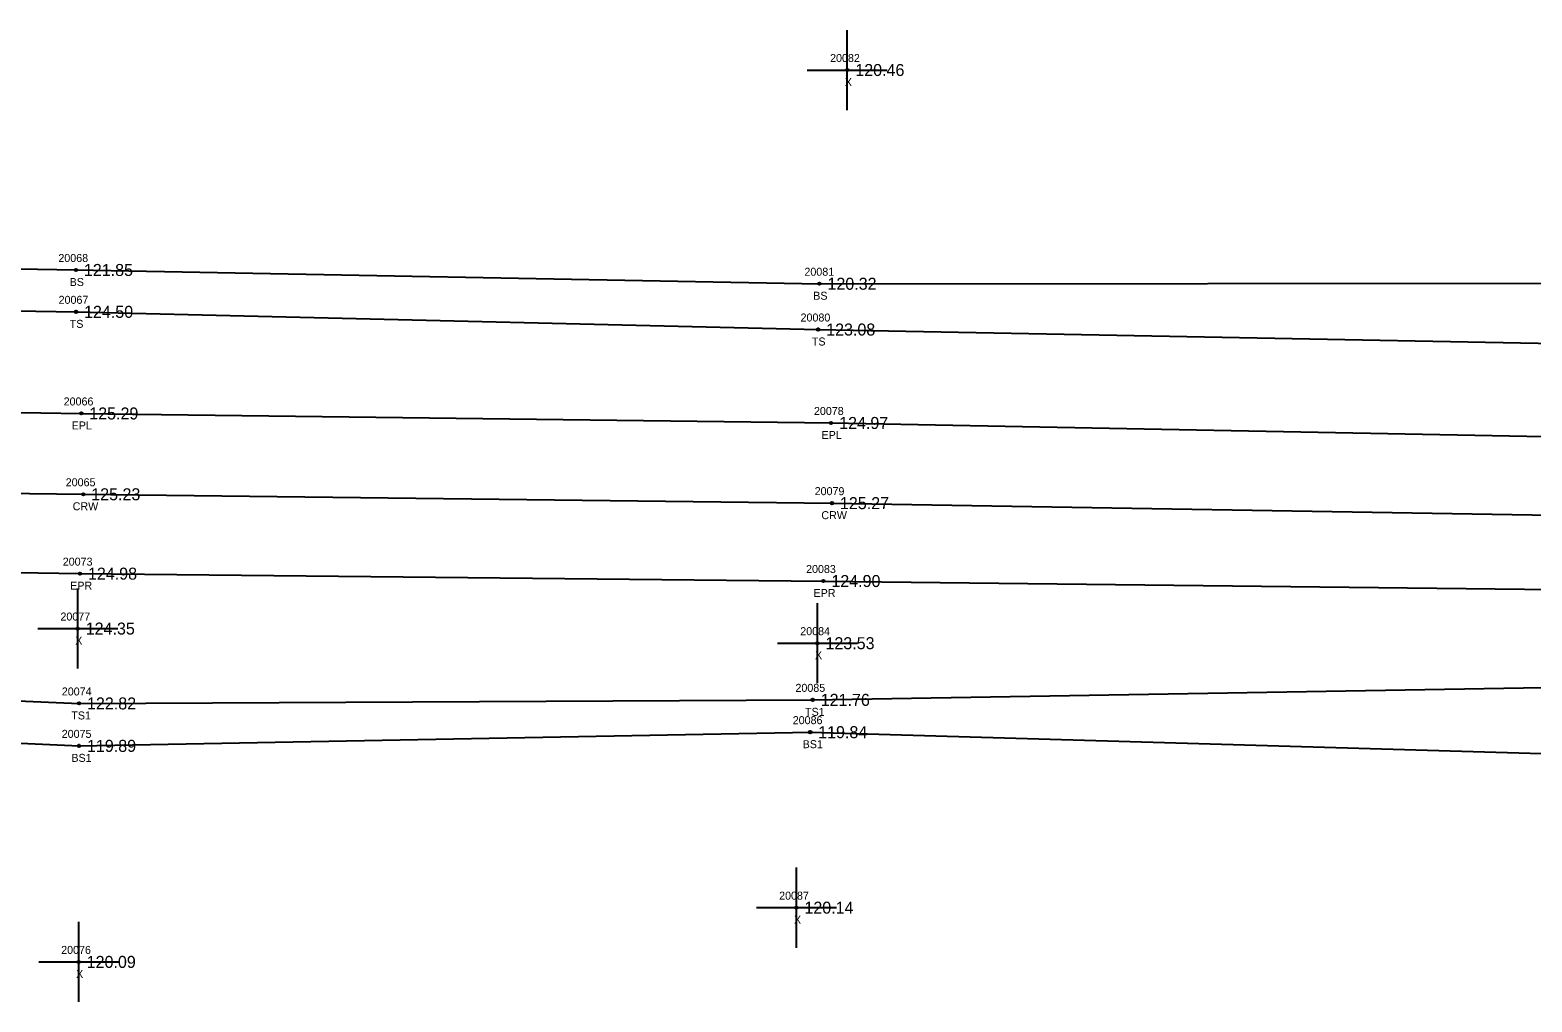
# Model space of a CAD drawing. Extents: x 2375812 to 2377225, y 1024470 to 1025135.
# Drawn here: x 2376214.8 to 2376402.6, y 1024867.7 to 1024989.2 of the extents above; entities that cross this region are included whole.
import ezdxf

# ---------------------------------------------------------------- set-up
doc = ezdxf.new("R2010")
doc.units = 0
for name, color, linetype in [('RD_DTM_BkLn1', 7, 'Continuous'), ('RD_DTM_BkLn2', 7, 'Continuous'), ('RD_DTM_BkLn_txCode', 7, 'Continuous'), ('RD_EX_Misc', 7, 'Continuous'), ('RD_EX_Misc_txCode', 7, 'Continuous'), ('RD_EX_Road', 7, 'Continuous'), ('RD_EX_Road_txCode', 7, 'Continuous'), ('RD_EX_TX_Misc_ELEV', 7, 'Continuous'), ('RD_EX_TX_Road_ELEV', 7, 'Continuous'), ('RD_HC_Survey_ELEV', 7, 'Continuous'), ('RD_HC_Survey_txCode', 7, 'Continuous'), ('RD_SMD_Locator', 7, 'Continuous')]:
    doc.layers.add(name, color=color, linetype=linetype)

msp = doc.modelspace()

# ---------------------------------------------------------------- linework, layer by layer
at = {"layer": 'RD_DTM_BkLn1'}
msp.add_lwpolyline([(2375816.52, 1024916.17), (2375868.08, 1024924.19), (2375918.61, 1024929.17), (2375973.79, 1024932.27), (2376030.31, 1024933.43), (2376124.39, 1024932.38), (2376221.5, 1024931.17), (2376315.07, 1024930.06), (2376410.07, 1024928.46), (2376471.65, 1024927.66)], dxfattribs=at)
at = {"layer": 'RD_DTM_BkLn2'}
for points in [[(2376029.54, 1024960.61), (2376031.93, 1024960.3), (2376124.75, 1024960.87), (2376220.58, 1024959.2), (2376313.51, 1024957.48), (2376410.53, 1024957.56), (2376415.87, 1024960.14)], [(2376030.33, 1024957.29), (2376124.82, 1024955.55), (2376220.6, 1024953.97), (2376313.35, 1024951.76), (2376409.92, 1024949.91), (2376424.84, 1024950.05)], [(2375828.21, 1024902.01), (2375869.58, 1024908.74), (2375919.97, 1024914.39), (2375974.42, 1024917.72), (2376030.13, 1024918.15), (2376124.55, 1024916.47), (2376157.47, 1024915.82), (2376169.1, 1024907.28), (2376220.97, 1024905.03), (2376312.67, 1024905.48), (2376408.92, 1024907.12), (2376437.56, 1024903.89), (2376467.32, 1024909.88), (2376471.6, 1024914.56)], [(2375828.74, 1024899.38), (2375869.85, 1024905.45), (2375920.89, 1024910.13), (2375974.62, 1024911.75), (2376029.89, 1024912.38), (2376123.86, 1024911.48), (2376128.27, 1024903.93), (2376220.97, 1024899.73), (2376312.35, 1024901.44), (2376410.93, 1024898.57), (2376439.29, 1024896.5), (2376469.35, 1024899.44), (2376491.09, 1024911.59)]]:
    msp.add_lwpolyline(points, dxfattribs=at)
at = {"layer": 'RD_EX_Misc'}
for p, q in [((2376316.99, 1024979.19), (2376316.99, 1024989.19)), ((2376311.99, 1024984.19), (2376321.99, 1024984.19)), ((2376220.81, 1024909.39), (2376220.81, 1024919.39)), ((2376313.26, 1024907.56), (2376313.26, 1024917.56)), ((2376215.81, 1024914.39), (2376225.81, 1024914.39)), ((2376308.26, 1024912.56), (2376318.26, 1024912.56)), ((2376310.63, 1024874.51), (2376310.63, 1024884.51)), ((2376305.63, 1024879.51), (2376315.63, 1024879.51)), ((2376220.93, 1024867.73), (2376220.93, 1024877.73)), ((2376215.93, 1024872.73), (2376225.93, 1024872.73))]:
    msp.add_line(p, q, dxfattribs=at)
at = {"layer": 'RD_EX_Road'}
for points in [[(2375814.75, 1024926.04), (2375866.75, 1024934.16), (2375917.59, 1024939.49), (2375973.63, 1024942.9), (2376030.48, 1024943.85), (2376125.42, 1024942.84), (2376221.25, 1024941.27), (2376314.97, 1024940.08), (2376410.64, 1024938.26), (2376471.87, 1024938.44)], [(2375818.02, 1024906.46), (2375868.67, 1024914.36), (2375919.37, 1024919.49), (2375974.01, 1024923.01), (2376030.21, 1024923.67), (2376124.55, 1024922.83), (2376221.09, 1024921.25), (2376314, 1024920.33), (2376408.92, 1024919.22), (2376471.42, 1024917.38)]]:
    msp.add_lwpolyline(points, dxfattribs=at)
at = {"layer": 'RD_SMD_Locator'}
for centre in [(2376316.99, 1024984.19), (2376220.58, 1024959.2), (2376313.51, 1024957.48), (2376220.6, 1024953.97), (2376313.35, 1024951.76), (2376221.25, 1024941.27), (2376314.97, 1024940.08), (2376221.5, 1024931.17), (2376315.07, 1024930.06), (2376221.09, 1024921.25), (2376314, 1024920.33), (2376220.81, 1024914.39), (2376313.26, 1024912.56), (2376312.67, 1024905.48), (2376220.97, 1024905.03), (2376312.35, 1024901.44), (2376220.97, 1024899.73), (2376310.63, 1024879.51), (2376220.93, 1024872.73)]:
    msp.add_circle(centre, 0.15, dxfattribs=at)

# ---------------------------------------------------------------- texts
at = {"layer": 'RD_DTM_BkLn_txCode'}
for s, p in [('20068', (2376218.39, 1024960.2)), ('BS', (2376219.8, 1024957.2)), ('20081', (2376311.63, 1024958.48)), ('BS', (2376312.73, 1024955.48)), ('20067', (2376218.42, 1024954.97)), ('TS', (2376219.81, 1024951.97)), ('20080', (2376311.15, 1024952.76)), ('TS', (2376312.56, 1024949.76)), ('20085', (2376310.51, 1024906.48)), ('20074', (2376218.82, 1024906.03)), ('TS1', (2376220.01, 1024903.03)), ('20086', (2376310.17, 1024902.44)), ('TS1', (2376311.71, 1024903.48)), ('20075', (2376218.81, 1024900.73)), ('BS1', (2376311.41, 1024899.44)), ('BS1', (2376220.02, 1024897.73))]:
    msp.add_text(s, height=1, dxfattribs=at).set_placement(p)
at = {"layer": 'RD_EX_Misc_txCode'}
for s, p in [('20082', (2376314.84, 1024985.19)), ('X', (2376316.68, 1024982.19)), ('20077', (2376218.65, 1024915.39)), ('X', (2376220.5, 1024912.39)), ('20084', (2376311.11, 1024913.56)), ('X', (2376312.95, 1024910.56)), ('20087', (2376308.47, 1024880.51)), ('X', (2376310.32, 1024877.51)), ('20076', (2376218.74, 1024873.73)), ('X', (2376220.61, 1024870.73))]:
    msp.add_text(s, height=1, dxfattribs=at).set_placement(p)
at = {"layer": 'RD_EX_Road_txCode'}
for s, p in [('20066', (2376219.05, 1024942.27)), ('20078', (2376312.82, 1024941.08)), ('EPL', (2376220.05, 1024939.27)), ('EPL', (2376313.77, 1024938.08)), ('20073', (2376218.94, 1024922.25)), ('20083', (2376311.84, 1024921.33)), ('EPR', (2376219.87, 1024919.25)), ('EPR', (2376312.77, 1024918.33))]:
    msp.add_text(s, height=1, dxfattribs=at).set_placement(p)
at = {"layer": 'RD_EX_TX_Misc_ELEV'}
for s, p in [('120.46', (2376317.99, 1024983.44)), ('121.85', (2376221.58, 1024958.45)), ('120.32', (2376314.51, 1024956.73)), ('124.50', (2376221.6, 1024953.22)), ('123.08', (2376314.35, 1024951.01)), ('124.35', (2376221.81, 1024913.64)), ('123.53', (2376314.26, 1024911.81)), ('122.82', (2376221.97, 1024904.28)), ('121.76', (2376313.67, 1024904.73)), ('119.84', (2376313.35, 1024900.69)), ('119.89', (2376221.97, 1024898.98)), ('120.14', (2376311.63, 1024878.76)), ('120.09', (2376221.93, 1024871.98))]:
    msp.add_text(s, height=1.5, dxfattribs=at).set_placement(p)
at = {"layer": 'RD_EX_TX_Road_ELEV'}
for s, p in [('125.29', (2376222.25, 1024940.52)), ('124.97', (2376315.97, 1024939.33)), ('124.98', (2376222.09, 1024920.5)), ('124.90', (2376315, 1024919.58))]:
    msp.add_text(s, height=1.5, dxfattribs=at).set_placement(p)
at = {"layer": 'RD_HC_Survey_ELEV'}
for s, p in [('125.23', (2376222.5, 1024930.42)), ('125.27', (2376316.07, 1024929.31))]:
    msp.add_text(s, height=1.5, dxfattribs=at).set_placement(p)
at = {"layer": 'RD_HC_Survey_txCode'}
for s, p in [('20065', (2376219.31, 1024932.17)), ('20079', (2376312.91, 1024931.06)), ('CRW', (2376220.18, 1024929.17)), ('CRW', (2376313.75, 1024928.06))]:
    msp.add_text(s, height=1, dxfattribs=at).set_placement(p)

doc.saveas('drawing.dxf')
